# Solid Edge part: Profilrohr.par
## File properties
Username: ahadarics
Dokumentum tartalom típus: 0
Author: ahadarics
Last saved by: ahadarics
Revision: 78
Sűrűség: 0,000 kg/m^3
Pontosság: 0,990
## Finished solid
Body 1: solid body, 6 faces, 6 edges, 0 vertices.
  Faces by surface: cone 2, cylinder 2, plane 2
  Edges by curve: circle 6
Bounding box of the edges (mm): 26.500 x 26.500 x 109.000, from (-13.25, -13.25, -74.5) to (13.25, 13.25, 34.5).
Cylindrical faces by radius (mm): R12.5 x1, R13.25 x1
Conical faces (half-angle, radius in mm at the cone's reference point): 15 deg R12.567 x2
Planar faces by outward normal: +z 1, -z 1
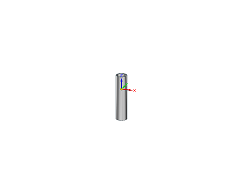
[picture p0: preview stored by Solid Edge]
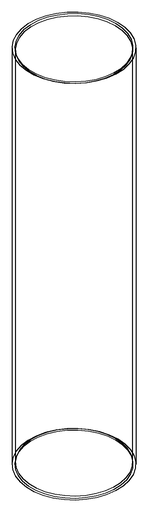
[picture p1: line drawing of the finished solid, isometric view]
